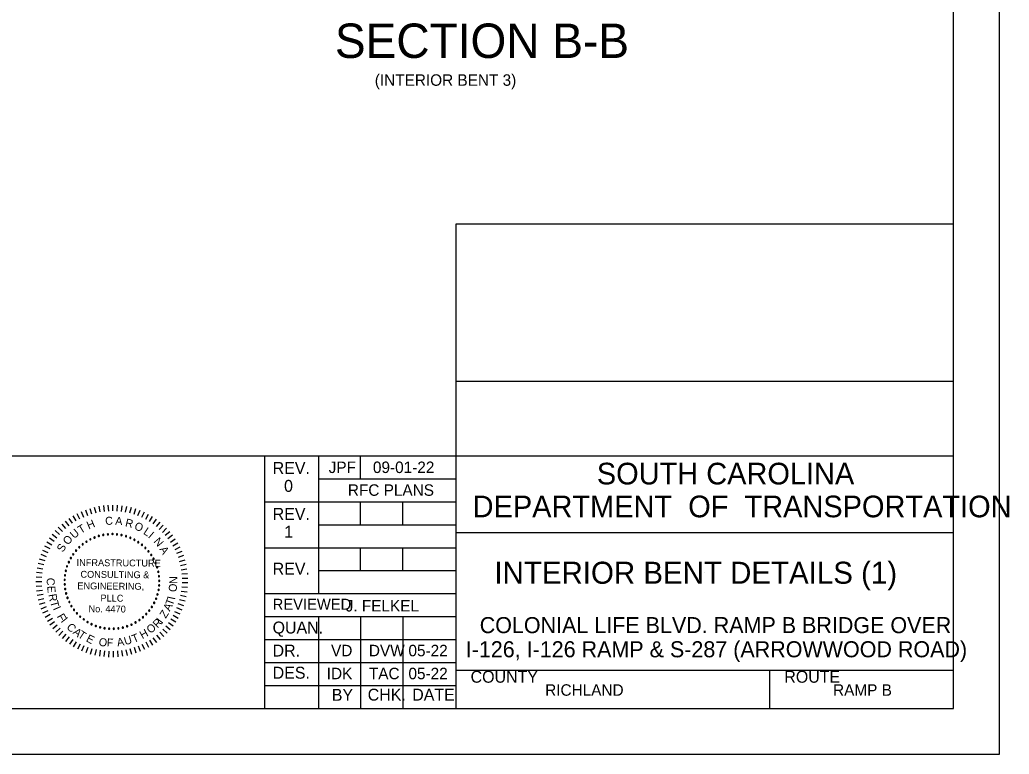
# Model space of a CAD drawing. Extents: x 1970675.2 to 1970711.3, y 796145.2 to 796167.2.
# Drawn here: x 1970700.57 to 1970711.34, y 796145.25 to 796153.25 of the extents above; entities that cross this region are included whole.
import ezdxf

# ---------------------------------------------------------------- set-up
doc = ezdxf.new("R2010")
doc.units = 0
for name, color, linetype in [('BR_BORDER LINES', 7, 'Continuous'), ('BR_TEXT', 7, 'Continuous'), ('Level 31', 7, 'Continuous')]:
    doc.layers.add(name, color=color, linetype=linetype)

msp = doc.modelspace()

# ---------------------------------------------------------------- linework, layer by layer
at = {"layer": 'BR_BORDER LINES'}
for p, q in [((1970710.736, 796145.746), (1970710.736, 796166.746)), ((1970705.319, 796145.746), (1970705.319, 796151.023)), ((1970705.319, 796151.023), (1970710.736, 796151.023)), ((1970705.319, 796149.308), (1970710.736, 796149.308)), ((1970697.87, 796148.496), (1970703.236, 796148.496)), ((1970703.236, 796145.746), (1970703.236, 796148.496)), ((1970703.236, 796148.496), (1970710.736, 796148.496)), ((1970703.819, 796148.496), (1970703.819, 796146.996)), ((1970704.277, 796148.246), (1970704.277, 796148.496)), ((1970703.819, 796148.246), (1970705.319, 796148.246)), ((1970703.236, 796147.996), (1970705.319, 796147.996)), ((1970704.277, 796147.746), (1970704.277, 796147.996)), ((1970704.736, 796147.746), (1970704.736, 796147.996)), ((1970703.819, 796147.746), (1970705.319, 796147.746)), ((1970705.319, 796147.663), (1970705.319, 796147.663)), ((1970705.319, 796147.663), (1970710.736, 796147.663)), ((1970703.236, 796147.496), (1970705.319, 796147.496)), ((1970704.277, 796147.246), (1970704.277, 796147.496)), ((1970704.736, 796147.246), (1970704.736, 796147.496)), ((1970703.819, 796147.246), (1970705.319, 796147.246)), ((1970703.236, 796146.996), (1970705.319, 796146.996)), ((1970703.236, 796146.746), (1970705.319, 796146.746)), ((1970703.819, 796146.746), (1970703.819, 796145.746)), ((1970704.277, 796146.746), (1970704.277, 796145.746)), ((1970704.736, 796146.746), (1970704.736, 796145.746)), ((1970703.236, 796146.496), (1970705.319, 796146.496)), ((1970703.236, 796146.246), (1970705.319, 796146.246)), ((1970705.319, 796146.163), (1970710.736, 796146.163)), ((1970705.417, 796146.163), (1970710.736, 796146.163)), ((1970708.736, 796145.746), (1970708.736, 796146.163)), ((1970703.236, 796145.996), (1970705.319, 796145.996)), ((1970677.07, 796145.746), (1970710.736, 796145.746))]:
    msp.add_line(p, q, dxfattribs=at)
at = {"layer": 'BR_TEXT'}
for p, q in [((1970701.233, 796147.889), (1970701.259, 796147.83)), ((1970701.28, 796147.908), (1970701.302, 796147.848)), ((1970701.328, 796147.924), (1970701.347, 796147.863)), ((1970701.377, 796147.937), (1970701.392, 796147.875)), ((1970701.426, 796147.947), (1970701.437, 796147.885)), ((1970701.476, 796147.955), (1970701.483, 796147.891)), ((1970701.526, 796147.959), (1970701.53, 796147.895)), ((1970701.577, 796147.96), (1970701.576, 796147.896)), ((1970701.627, 796147.958), (1970701.623, 796147.894)), ((1970701.678, 796147.953), (1970701.669, 796147.889)), ((1970701.727, 796147.944), (1970701.715, 796147.882)), ((1970701.777, 796147.933), (1970701.761, 796147.872)), ((1970701.825, 796147.919), (1970701.806, 796147.859)), ((1970701.873, 796147.902), (1970701.849, 796147.843)), ((1970701.061, 796147.785), (1970701.1, 796147.735)), ((1970701.101, 796147.815), (1970701.137, 796147.762)), ((1970701.144, 796147.842), (1970701.177, 796147.788)), ((1970701.188, 796147.867), (1970701.217, 796147.81)), ((1970701.919, 796147.882), (1970701.892, 796147.824)), ((1970701.964, 796147.859), (1970701.934, 796147.803)), ((1970702.008, 796147.834), (1970701.974, 796147.78)), ((1970702.05, 796147.806), (1970702.013, 796147.754)), ((1970700.95, 796147.682), (1970700.998, 796147.639)), ((1970700.985, 796147.718), (1970701.03, 796147.673)), ((1970701.022, 796147.753), (1970701.064, 796147.705)), ((1970702.09, 796147.775), (1970702.05, 796147.726)), ((1970702.128, 796147.742), (1970702.085, 796147.695)), ((1970702.164, 796147.707), (1970702.119, 796147.663)), ((1970700.888, 796147.602), (1970700.94, 796147.566)), ((1970700.918, 796147.643), (1970700.968, 796147.604)), ((1970702.198, 796147.67), (1970702.15, 796147.628)), ((1970702.23, 796147.631), (1970702.179, 796147.592)), ((1970702.259, 796147.589), (1970702.206, 796147.554)), ((1970700.814, 796147.47), (1970700.872, 796147.445)), ((1970700.836, 796147.516), (1970700.892, 796147.486)), ((1970700.861, 796147.56), (1970700.915, 796147.527)), ((1970702.286, 796147.546), (1970702.231, 796147.514)), ((1970702.31, 796147.502), (1970702.253, 796147.473)), ((1970700.778, 796147.376), (1970700.839, 796147.357)), ((1970700.795, 796147.424), (1970700.854, 796147.401)), ((1970702.331, 796147.456), (1970702.272, 796147.431)), ((1970702.349, 796147.409), (1970702.289, 796147.388)), ((1970702.364, 796147.361), (1970702.303, 796147.343)), ((1970700.754, 796147.278), (1970700.817, 796147.267)), ((1970700.765, 796147.327), (1970700.827, 796147.312)), ((1970702.377, 796147.312), (1970702.315, 796147.298)), ((1970702.386, 796147.263), (1970702.324, 796147.252)), ((1970700.743, 796147.178), (1970700.806, 796147.174)), ((1970700.747, 796147.228), (1970700.81, 796147.221)), ((1970702.393, 796147.212), (1970702.33, 796147.206)), ((1970702.396, 796147.162), (1970702.333, 796147.16)), ((1970700.741, 796147.127), (1970700.805, 796147.128)), ((1970700.743, 796147.077), (1970700.807, 796147.081)), ((1970700.748, 796147.027), (1970700.811, 796147.035)), ((1970702.394, 796147.061), (1970702.33, 796147.067)), ((1970702.397, 796147.112), (1970702.333, 796147.113)), ((1970700.756, 796146.977), (1970700.819, 796146.989)), ((1970700.767, 796146.927), (1970700.829, 796146.943)), ((1970702.367, 796146.912), (1970702.306, 796146.929)), ((1970702.379, 796146.961), (1970702.317, 796146.974)), ((1970702.388, 796147.011), (1970702.325, 796147.02)), ((1970700.781, 796146.879), (1970700.842, 796146.898)), ((1970700.798, 796146.831), (1970700.857, 796146.855)), ((1970700.818, 796146.785), (1970700.875, 796146.812)), ((1970702.334, 796146.817), (1970702.276, 796146.841)), ((1970702.352, 796146.864), (1970702.292, 796146.885)), ((1970700.84, 796146.74), (1970700.896, 796146.77)), ((1970700.866, 796146.696), (1970700.92, 796146.73)), ((1970702.264, 796146.683), (1970702.211, 796146.717)), ((1970702.29, 796146.726), (1970702.235, 796146.757)), ((1970702.314, 796146.771), (1970702.256, 796146.798)), ((1970700.893, 796146.654), (1970700.945, 796146.691)), ((1970700.924, 796146.614), (1970700.973, 796146.654)), ((1970700.957, 796146.575), (1970701.004, 796146.618)), ((1970702.171, 796146.564), (1970702.125, 796146.607)), ((1970702.204, 796146.602), (1970702.155, 796146.642)), ((1970702.236, 796146.641), (1970702.184, 796146.679)), ((1970700.992, 796146.539), (1970701.036, 796146.585)), ((1970701.029, 796146.505), (1970701.07, 796146.553)), ((1970701.068, 796146.473), (1970701.107, 796146.524)), ((1970701.109, 796146.444), (1970701.145, 796146.497)), ((1970702.016, 796146.435), (1970701.981, 796146.489)), ((1970702.057, 796146.464), (1970702.02, 796146.515)), ((1970702.097, 796146.495), (1970702.057, 796146.544)), ((1970702.135, 796146.528), (1970702.092, 796146.575)), ((1970701.152, 796146.417), (1970701.184, 796146.472)), ((1970701.196, 796146.393), (1970701.225, 796146.45)), ((1970701.242, 796146.372), (1970701.267, 796146.43)), ((1970701.289, 796146.353), (1970701.311, 796146.413)), ((1970701.337, 796146.337), (1970701.355, 796146.399)), ((1970701.386, 796146.325), (1970701.4, 796146.387)), ((1970701.737, 796146.322), (1970701.724, 796146.384)), ((1970701.786, 796146.333), (1970701.769, 796146.395)), ((1970701.834, 796146.348), (1970701.814, 796146.408)), ((1970701.881, 796146.366), (1970701.857, 796146.424)), ((1970701.928, 796146.386), (1970701.9, 796146.443)), ((1970701.972, 796146.409), (1970701.941, 796146.465)), ((1970701.436, 796146.315), (1970701.446, 796146.378)), ((1970701.486, 796146.309), (1970701.492, 796146.372)), ((1970701.536, 796146.305), (1970701.538, 796146.369)), ((1970701.586, 796146.305), (1970701.585, 796146.368)), ((1970701.637, 796146.307), (1970701.632, 796146.371)), ((1970701.687, 796146.313), (1970701.678, 796146.376))]:
    msp.add_line(p, q, dxfattribs=at)
for centre, start, end in [((1970701.291, 796147.562), 32.7576, 212.7576), ((1970701.291, 796147.562), 212.7576, 32.7576), ((1970701.334, 796147.587), 27.2191, 207.2191), ((1970701.334, 796147.587), 207.2191, 27.2191), ((1970701.38, 796147.607), 21.6807, 201.6807), ((1970701.38, 796147.607), 201.6807, 21.6807), ((1970701.427, 796147.624), 16.1422, 196.1422), ((1970701.427, 796147.624), 196.1422, 16.1422), ((1970701.475, 796147.635), 10.6038, 190.6038), ((1970701.475, 796147.635), 190.6038, 10.6038), ((1970701.525, 796147.642), 5.0653, 185.0653), ((1970701.525, 796147.642), 185.0653, 5.0653), ((1970701.575, 796147.644), 359.5268, 179.5268), ((1970701.575, 796147.644), 179.5268, 359.5268), ((1970701.624, 796147.641), 353.9884, 173.9884), ((1970701.624, 796147.641), 173.9884, 353.9884), ((1970701.673, 796147.633), 168.4499, 348.4499), ((1970701.673, 796147.633), 348.4499, 168.4499), ((1970701.722, 796147.621), 342.9114, 162.9114), ((1970701.722, 796147.621), 162.9114, 342.9114), ((1970701.769, 796147.604), 337.373, 157.373), ((1970701.769, 796147.604), 157.373, 337.373), ((1970701.814, 796147.582), 331.8345, 151.8345), ((1970701.814, 796147.582), 151.8345, 331.8345), ((1970701.178, 796147.464), 49.373, 229.373), ((1970701.178, 796147.464), 229.373, 49.373), ((1970701.213, 796147.501), 43.8345, 223.8345), ((1970701.213, 796147.501), 223.8345, 43.8345), ((1970701.25, 796147.533), 38.2961, 218.2961), ((1970701.25, 796147.533), 218.2961, 38.2961), ((1970701.856, 796147.556), 146.2961, 326.2961), ((1970701.856, 796147.556), 326.2961, 146.2961), ((1970701.896, 796147.527), 140.7576, 320.7576), ((1970701.896, 796147.527), 320.7576, 140.7576), ((1970701.933, 796147.493), 135.2191, 315.2191), ((1970701.933, 796147.493), 315.2191, 135.2191), ((1970701.967, 796147.456), 129.6807, 309.6807), ((1970701.967, 796147.456), 309.6807, 129.6807), ((1970701.121, 796147.383), 60.4499, 240.4499), ((1970701.121, 796147.383), 240.4499, 60.4499), ((1970701.148, 796147.425), 54.9114, 234.9114), ((1970701.148, 796147.425), 234.9114, 54.9114), ((1970701.997, 796147.416), 124.1422, 304.1422), ((1970701.997, 796147.416), 304.1422, 124.1422), ((1970702.022, 796147.374), 118.6038, 298.6038), ((1970702.022, 796147.374), 298.6038, 118.6038), ((1970701.067, 796147.244), 77.0653, 257.0653), ((1970701.067, 796147.244), 257.0653, 77.0653), ((1970701.08, 796147.292), 71.5268, 251.5268), ((1970701.08, 796147.292), 251.5268, 71.5268), ((1970701.099, 796147.339), 65.9884, 245.9884), ((1970701.099, 796147.339), 245.9884, 65.9884), ((1970702.044, 796147.329), 113.0653, 293.0653), ((1970702.044, 796147.329), 293.0653, 113.0653), ((1970702.061, 796147.282), 107.5268, 287.5268), ((1970702.061, 796147.282), 287.5268, 107.5268), ((1970701.054, 796147.146), 88.1422, 268.1422), ((1970701.058, 796147.195), 82.6038, 262.6038), ((1970701.054, 796147.146), 268.1422, 88.1422), ((1970701.058, 796147.195), 262.6038, 82.6038), ((1970702.074, 796147.234), 101.9884, 281.9884), ((1970702.074, 796147.234), 281.9884, 101.9884), ((1970702.082, 796147.185), 96.4499, 276.4499), ((1970702.085, 796147.135), 90.9114, 270.9114), ((1970702.082, 796147.185), 276.4499, 96.4499), ((1970702.085, 796147.135), 270.9114, 90.9114), ((1970701.055, 796147.096), 93.6807, 273.6807), ((1970701.06, 796147.046), 99.2191, 279.2191), ((1970701.055, 796147.096), 273.6807, 93.6807), ((1970701.06, 796147.046), 279.2191, 99.2191), ((1970702.077, 796147.036), 79.8345, 259.8345), ((1970702.077, 796147.036), 259.8345, 79.8345), ((1970702.083, 796147.085), 85.373, 265.373), ((1970702.083, 796147.085), 265.373, 85.373), ((1970701.07, 796146.998), 104.7576, 284.7576), ((1970701.07, 796146.998), 284.7576, 104.7576), ((1970701.085, 796146.95), 110.2961, 290.2961), ((1970701.085, 796146.95), 290.2961, 110.2961), ((1970702.05, 796146.94), 68.7576, 248.7576), ((1970702.05, 796146.94), 248.7576, 68.7576), ((1970702.065, 796146.987), 74.2961, 254.2961), ((1970702.065, 796146.987), 254.2961, 74.2961), ((1970701.105, 796146.904), 115.8345, 295.8345), ((1970701.105, 796146.904), 295.8345, 115.8345), ((1970701.128, 796146.86), 121.373, 301.373), ((1970701.128, 796146.86), 301.373, 121.373), ((1970701.156, 796146.819), 126.9114, 306.9114), ((1970701.156, 796146.819), 306.9114, 126.9114), ((1970701.976, 796146.811), 52.1422, 232.1422), ((1970701.976, 796146.811), 232.1422, 52.1422), ((1970702.004, 796146.851), 57.6807, 237.6807), ((1970702.004, 796146.851), 237.6807, 57.6807), ((1970702.029, 796146.895), 63.2191, 243.2191), ((1970702.029, 796146.895), 243.2191, 63.2191), ((1970701.188, 796146.781), 132.4499, 312.4499), ((1970701.188, 796146.781), 312.4499, 132.4499), ((1970701.223, 796146.745), 137.9884, 317.9884), ((1970701.223, 796146.745), 317.9884, 137.9884), ((1970701.262, 796146.714), 143.5268, 323.5268), ((1970701.262, 796146.714), 323.5268, 143.5268), ((1970701.868, 796146.708), 35.5268, 215.5268), ((1970701.868, 796146.708), 215.5268, 35.5268), ((1970701.907, 796146.738), 41.0653, 221.0653), ((1970701.907, 796146.738), 221.0653, 41.0653), ((1970701.943, 796146.773), 46.6038, 226.6038), ((1970701.943, 796146.773), 226.6038, 46.6038), ((1970701.303, 796146.686), 149.0653, 329.0653), ((1970701.303, 796146.686), 329.0653, 149.0653), ((1970701.347, 796146.662), 154.6038, 334.6038), ((1970701.347, 796146.662), 334.6038, 154.6038), ((1970701.393, 796146.643), 340.1422, 160.1422), ((1970701.393, 796146.643), 160.1422, 340.1422), ((1970701.441, 796146.628), 345.6807, 165.6807), ((1970701.441, 796146.628), 165.6807, 345.6807), ((1970701.489, 796146.618), 171.2191, 351.2191), ((1970701.489, 796146.618), 351.2191, 171.2191), ((1970701.539, 796146.613), 356.7576, 176.7576), ((1970701.539, 796146.613), 176.7576, 356.7576), ((1970701.589, 796146.613), 2.2961, 182.2961), ((1970701.589, 796146.613), 182.2961, 2.2961), ((1970701.639, 796146.617), 7.8345, 187.8345), ((1970701.639, 796146.617), 187.8345, 7.8345), ((1970701.688, 796146.626), 13.373, 193.373), ((1970701.688, 796146.626), 193.373, 13.373), ((1970701.735, 796146.64), 18.9114, 198.9114), ((1970701.735, 796146.64), 198.9114, 18.9114), ((1970701.782, 796146.658), 24.4499, 204.4499), ((1970701.782, 796146.658), 204.4499, 24.4499), ((1970701.826, 796146.681), 29.9884, 209.9884), ((1970701.826, 796146.681), 209.9884, 29.9884)]:
    msp.add_arc(centre, 0.00701, start, end, dxfattribs=at)
at = {"layer": 'Level 31'}
msp.add_line((1970708.028, 796147.223), (1970708.028, 796147.223), dxfattribs=at)
msp.add_lwpolyline([(1970675.236, 796145.246), (1970711.236, 796145.246), (1970711.236, 796167.246), (1970675.236, 796167.246)], close=True, dxfattribs=at)

# ---------------------------------------------------------------- texts
at = {"layer": 'BR_TEXT'}
for s, height, p in [('SECTION B-B', 0.375, (1970703.998, 796152.83)), ('REV.', 0.13, (1970703.32, 796148.299)), ('JPF', 0.125, (1970703.93, 796148.309)), ('09-01-22', 0.125, (1970704.412, 796148.309)), ('SOUTH CAROLINA', 0.23587, (1970706.851, 796148.185)), ('0', 0.13, (1970703.444, 796148.104)), ('RFC PLANS', 0.125, (1970704.139, 796148.061)), ('DEPARTMENT  OF  TRANSPORTATION', 0.23587, (1970705.498, 796147.827)), ('REV.', 0.13, (1970703.32, 796147.799)), ('1', 0.13, (1970703.446, 796147.604)), ('INTERIOR BENT DETAILS (1)', 0.24, (1970705.735, 796147.103)), ('REV.', 0.13, (1970703.32, 796147.202)), ('REVIEWED', 0.12, (1970703.32, 796146.82)), ('J. FELKEL', 0.125, (1970704.115, 796146.801)), ('COLONIAL LIFE BLVD. RAMP B BRIDGE OVER', 0.175, (1970705.575, 796146.565)), ('QUAN.', 0.13, (1970703.319, 796146.561)), ('DR.', 0.13, (1970703.319, 796146.31)), ('VD', 0.125, (1970703.956, 796146.313)), ('DVW', 0.125, (1970704.368, 796146.313)), ('05-22', 0.125, (1970704.799, 796146.313)), ('I-126, I-126 RAMP & S-287 (ARROWWOOD ROAD) ', 0.175, (1970705.423, 796146.302)), ('DES.', 0.13, (1970703.32, 796146.069)), ('IDK', 0.125, (1970703.909, 796146.063)), ('TAC', 0.125, (1970704.368, 796146.063)), ('05-22', 0.125, (1970704.799, 796146.063)), ('COUNTY', 0.13, (1970705.476, 796146.025)), ('ROUTE', 0.13, (1970708.893, 796146.025)), ('BY', 0.13, (1970703.964, 796145.828)), ('CHK.', 0.13, (1970704.355, 796145.83)), ('DATE', 0.13, (1970704.84, 796145.83)), ('RICHLAND', 0.125, (1970706.288, 796145.883)), ('RAMP B', 0.125, (1970709.424, 796145.883))]:
    msp.add_text(s, height=height, dxfattribs=at).set_placement(p)
for s, height, rotation, p in [('(INTERIOR BENT 3)', 0.125, 360, (1970704.432, 796152.527)), ('H', 0.0872, 22.7882, (1970701.316, 796147.693)), ('C', 0.0872, 4.7281, (1970701.499, 796147.742)), ('A', 0.0872, 355.6981, (1970701.603, 796147.747)), ('R', 0.0872, 346.6681, (1970701.708, 796147.73)), ('U', 0.0872, 40.8482, (1970701.158, 796147.589)), ('T', 0.0872, 31.8182, (1970701.231, 796147.645)), ('O', 0.0872, 337.638, (1970701.805, 796147.7)), ('L', 0.0872, 327.108, (1970701.904, 796147.65)), ('O', 0.0872, 49.8782, (1970701.091, 796147.518)), ('I', 0.0872, 319.578, (1970701.957, 796147.612)), ('N', 0.0872, 310.548, (1970702.018, 796147.561)), ('S', 0.0872, 58.9083, (1970701.036, 796147.44)), ('A', 0.0872, 301.5179, (1970702.083, 796147.479)), ('INFRASTRUCTURE', 0.07477, 359.5268, (1970701.184, 796147.297)), ('CONSULTING &', 0.07477, 359.5268, (1970701.226, 796147.169)), ('C', 0.0872, 267.025, (1970700.861, 796147.17)), ('N', 0.0872, 89.2085, (1970702.282, 796147.1)), ('E', 0.0872, 273.025, (1970700.865, 796147.078)), ('ENGINEERING,', 0.07477, 359.5268, (1970701.192, 796147.043)), ('O', 0.0872, 83.2085, (1970702.271, 796147.009)), ('R', 0.0872, 279.025, (1970700.878, 796146.986)), ('T', 0.0872, 285.025, (1970700.895, 796146.907)), ('PLLC', 0.0748, 359.5268, (1970701.444, 796146.91)), ('T', 0.0872, 69.3954, (1970702.23, 796146.857)), ('I', 0.0872, 77.9093, (1970702.255, 796146.924)), ('I', 0.0872, 293.7713, (1970700.925, 796146.834)), ('No. 4470', 0.0748, 359.5268, (1970701.314, 796146.793)), ('Z', 0.0872, 57.3954, (1970702.155, 796146.72)), ('A', 0.0872, 63.3954, (1970702.199, 796146.797)), ('F', 0.0872, 299.7713, (1970700.966, 796146.748)), ('I', 0.0872, 308.5268, (1970701.008, 796146.694)), ('R', 0.0872, 44.5268, (1970702.065, 796146.615)), ('I', 0.0872, 52.3339, (1970702.114, 796146.662)), ('C', 0.0872, 314.5268, (1970701.068, 796146.624)), ('A', 0.0872, 320.5268, (1970701.137, 796146.565)), ('T', 0.0872, 326.5268, (1970701.191, 796146.527)), ('H', 0.0872, 28.5268, (1970701.9, 796146.499)), ('O', 0.0872, 38.5268, (1970701.988, 796146.555)), ('E', 0.0872, 332.5268, (1970701.28, 796146.479)), ('O', 0.0872, 350.5268, (1970701.42, 796146.43)), ('F', 0.0872, 356.5268, (1970701.511, 796146.421)), ('A', 0.0872, 10.5268, (1970701.631, 796146.42)), ('U', 0.0872, 16.5268, (1970701.715, 796146.433)), ('T', 0.0872, 22.5268, (1970701.807, 796146.457))]:
    msp.add_text(s, height=height, rotation=rotation, dxfattribs=at).set_placement(p)

doc.saveas('drawing.dxf')
